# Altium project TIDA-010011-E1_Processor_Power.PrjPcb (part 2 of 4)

## Sheet TIDA-010011-E1_Processor_Power _Pg5.SchDoc: COMPACT POWER MODULE
size 431 x 279 mm; Date: Not shown in title block; ApprovedBy: Not shown in title block; CheckedBy: Not shown in title block; Author: Not shown in title block; CompanyName: Not shown in title block; DrawnBy: Sreenivasa; Engineer: Not shown in title block; Organization: Not shown in title block; Address1: Not shown in title block; Address2: Not shown in title block; Address3: Not shown in title block; Address4: Not shown in title block; DocumentNumber: 1; Revision: Use project parameter SCH_Rev; SheetNumber: 5; SheetTotal: 12; PageSetup: Record=PageOptions¦CenterHorizontal=True¦CenterVertical=True¦PrintScale=0.62¦XCorrection=1.00¦YCorrection=1.00¦PrintKind=0¦BorderSize=5000000¦LeftOffset=0¦BottomOffset=0¦Orientation=2¦PaperLength=1000¦PaperWidth=1000¦Scale=100¦PaperSource=15¦PrintQuality=600¦MediaType=1¦DitherType=10¦PrintScaleMode=1¦PaperKind=Letter
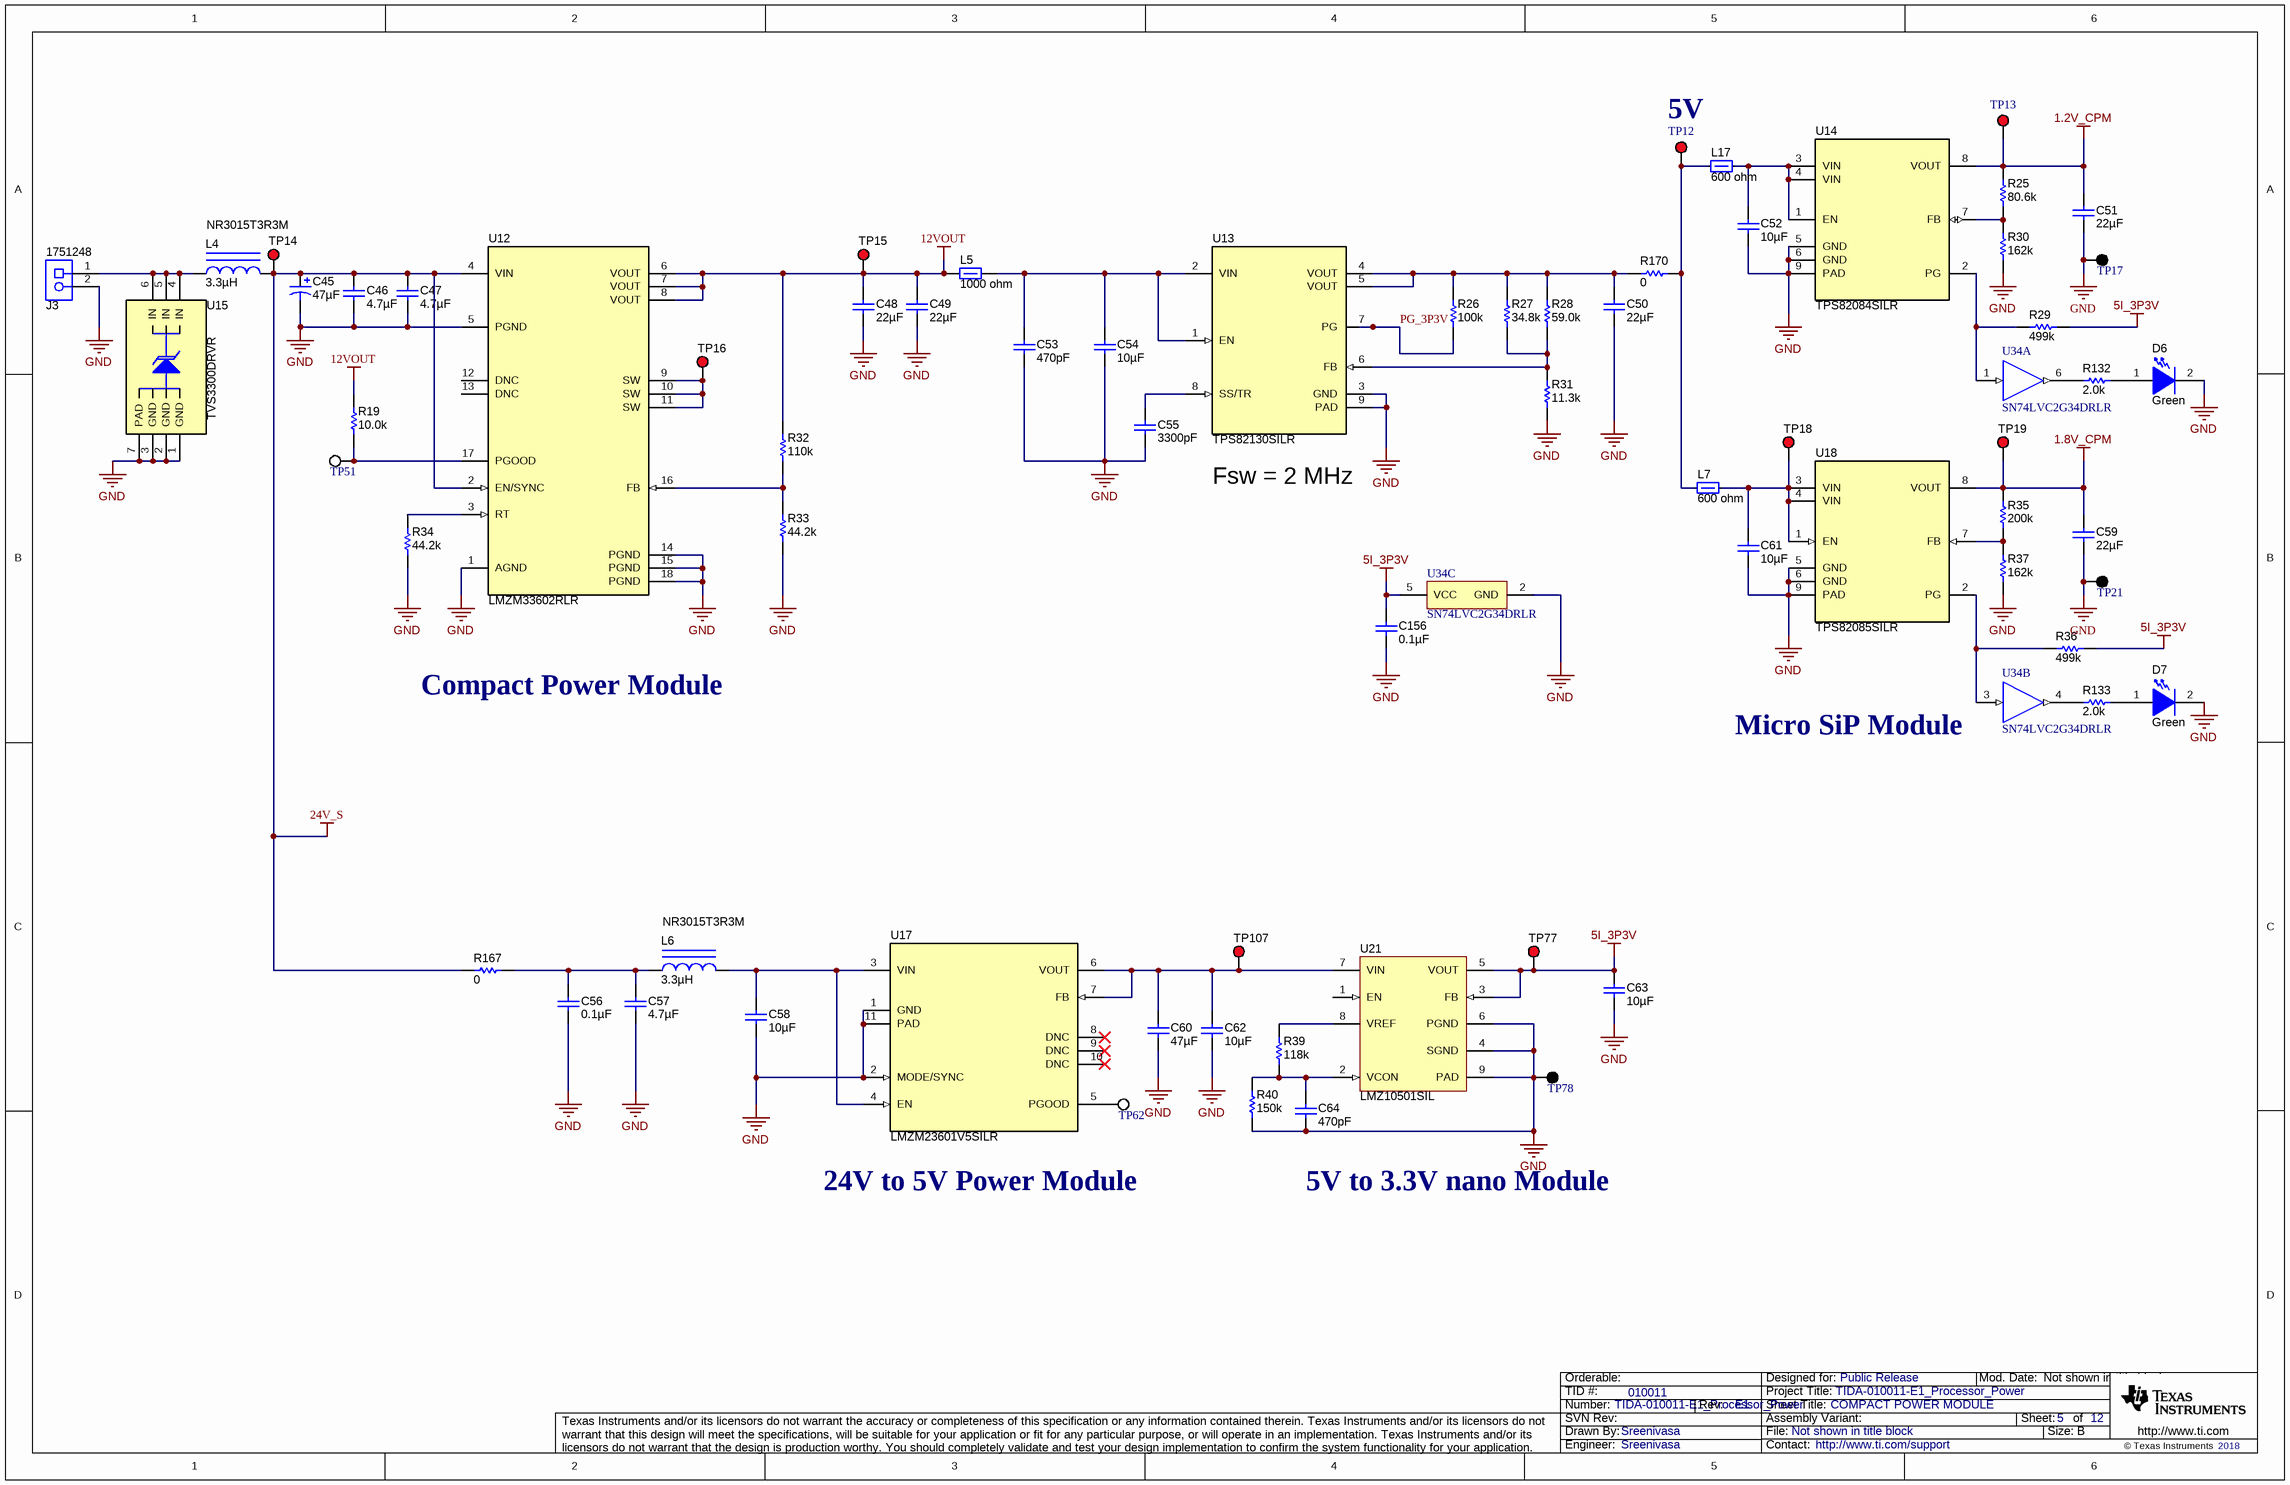
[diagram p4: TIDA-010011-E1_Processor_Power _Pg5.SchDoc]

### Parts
C45  ValueDisplayed: 47µF  [KZN_800x1500]  (hidden comment: EKZN101ELL470MH15D)
C46  ValueDisplayed: 4.7µF  [1210_270]  (hidden comment: GRM32ER71H475KA88L)
C47  ValueDisplayed: 4.7µF  [1210_270]  (hidden comment: GRM32ER71H475KA88L)
C48  ValueDisplayed: 22µF  [1210_270]  (hidden comment: GRM32ER71E226KE15L)
C49  ValueDisplayed: 22µF  [1210_270]  (hidden comment: GRM32ER71E226KE15L)
C50  ValueDisplayed: 22µF  [0805_HV]  (hidden comment: JMK212BJ226MG-T)
C51  ValueDisplayed: 22µF  [0805_HV]  (hidden comment: JMK212BJ226KG-T)
C52  ValueDisplayed: 10µF  [0805_HV]  (hidden comment: GRM21BR71A106KE51L)
C53  ValueDisplayed: 470pF  [0402]  (hidden comment: GRM1555C1H471JA01D)
C54  ValueDisplayed: 10µF  [1206_190]  (hidden comment: C3216X7R1E106M160AE)
C55  ValueDisplayed: 3300pF  [0603]  (hidden comment: GRM1885C1H332JA01D)
C56  ValueDisplayed: 0.1µF  [0805_HV]  (hidden comment: C2012X7R2A104K125AA)
C57  ValueDisplayed: 4.7µF  [1206]  (hidden comment: C3216X7R1V475K085AC)
C58  ValueDisplayed: 10µF  [1206_180]  (hidden comment: CL31B106KBHNNNE)
C59  ValueDisplayed: 22µF  [0805_HV]  (hidden comment: JMK212BJ226KG-T)
C60  ValueDisplayed: 47µF  [1206]  (hidden comment: C3216X5R1C476M160AB)
C61  ValueDisplayed: 10µF  [0805_HV]  (hidden comment: GRM21BR71A106KE51L)
C62  ValueDisplayed: 10µF  [0603]  (hidden comment: C1608X5R1E106M080AC)
C63  ValueDisplayed: 10µF  [0603]  (hidden comment: C1608X5R1E106M080AC)
C64  ValueDisplayed: 470pF  [0603]  (hidden comment: GRM188R71H471KA01D)
C156  ValueDisplayed: 0.1µF  [0603]  (hidden comment: 06033D104KAT2A)
D6  value Green  [LED_LTST-C190_G]  (hidden comment: LTST-C190KGKT)
D7  value Green  [LED_LTST-C190_G]  (hidden comment: LTST-C190KGKT)
J3  1751248  [CONN_1751248]
L4  NR3015T3R3M  ValueDisplayed: 3.3µH  [NR3015]
L5  ValueDisplayed: 1000 ohm  [1806_HighSpeed]  (hidden comment: BLM41PG102SN1L)
L6  NR3015T3R3M  ValueDisplayed: 3.3µH  [NR3015]
L7  value 600 ohm  [0805_HV]  (hidden comment: MPZ2012S601A)
L17  value 600 ohm  [0805_HV]  (hidden comment: MPZ2012S601A)
R19  ValueDisplayed: 10.0k  [0402]  (hidden comment: CRCW040210K0FKED)
R25  ValueDisplayed: 80.6k  [0603]  (hidden comment: RC0603FR-0780K6L)
R26  ValueDisplayed: 100k  [0402]  (hidden comment: CRCW0402100KFKED)
R27  ValueDisplayed: 34.8k  [0603]  (hidden comment: CRCW060334K8FKEA)
R28  ValueDisplayed: 59.0k  [0402]  (hidden comment: CRCW040259K0FKED)
R29  ValueDisplayed: 499k  [0603]  (hidden comment: ERJ-3EKF4993V)
R30  ValueDisplayed: 162k  [0603]  (hidden comment: RC0603FR-07162KL)
R31  ValueDisplayed: 11.3k  [0402]  (hidden comment: CRCW040211K3FKED)
R32  ValueDisplayed: 110k  [0603]  (hidden comment: RC0603FR-07110KL)
R33  ValueDisplayed: 44.2k  [0603]  (hidden comment: CRCW060344K2FKEA)
R34  ValueDisplayed: 44.2k  [0603]  (hidden comment: CRCW060344K2FKEA)
R35  ValueDisplayed: 200k  [0603]  (hidden comment: RC0603FR-07200KL)
R36  ValueDisplayed: 499k  [0603]  (hidden comment: ERJ-3EKF4993V)
R37  ValueDisplayed: 162k  [0603]  (hidden comment: RC0603FR-07162KL)
R39  ValueDisplayed: 118k  [0402]  (hidden comment: CRCW0402118KFKED)
R40  ValueDisplayed: 150k  [0402]  (hidden comment: CRCW0402150KFKED)
R132  ValueDisplayed: 2.0k  [0603]  (hidden comment: CRCW06032K00JNEA)
R133  ValueDisplayed: 2.0k  [0603]  (hidden comment: CRCW06032K00JNEA)
R167  ValueDisplayed: 0  [0805_HV]  (hidden comment: CRCW08050000Z0EA)
R170  ValueDisplayed: 0  [0805_HV]  (hidden comment: CRCW08050000Z0EA)
TP12  5000  [Keystone5000]  (value not drawn)
TP13  5000  [Keystone5000]  (value not drawn)
TP14  (no value)  [Keystone5000]
TP15  (no value)  [Keystone5000]
TP16  (no value)  [Keystone5000]
TP17  5001  [Keystone5001]  (value not drawn)
TP18  (no value)  [Keystone5000]
TP19  (no value)  [Keystone5000]
TP21  5001  [Keystone5001]  (value not drawn)
TP51  5002  [Keystone5002]  (value not drawn)
TP62  5002  [Keystone5002]  (value not drawn)
TP77  (no value)  [Keystone5000]
TP78  5001  [Keystone5001]  (value not drawn)
TP107  (no value)  [Keystone5000]
U12  LMZM33602RLR  [RLR0018A]
U13  TPS82130SILR  [SIL0008D_SMD]
U14  TPS82084SILR  [SIL0008C_SMD]
U15  TVS3300DRVR  [DRV0006A]
U17  LMZM23601V5SILR  [SIL0010A]
U18  TPS82085SILR  [SIL0008C_SMD]
U21  LMZ10501SIL  [SIL0008A]
U34  SN74LVC2G34DRLR  [DRL0006A]  (parts A,B,C of 3)

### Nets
1.2V_CPM: C51.1 R25.2 TP13.1 U14.8(VOUT)
1.8V_CPM: C59.1 R35.2 TP19.1 U18.8(VOUT)
5I_3P3V: C63.1 C156.1 R29.2 R36.1 TP77.1 U21.3(FB) U21.5(VOUT) U34.5(VCC)
12VOUT: C48.1 C49.1 L5.2 R19.2 R32.2 TP15.1 U12.6(VOUT) U12.7(VOUT) U12.8(VOUT)
24V_S: C45.1(+) C46.1 C47.1 L4.2 R167.2 TP14.1 U12.2(EN/SYNC) U12.4(VIN)
GND: C45.2(-) C46.2 C47.2 C48.2 C49.2 C50.2 C51.2 C52.2 C53.2 C54.2 C55.1 C56.2 C57.2 C58.2 C59.2 C60.2 C61.2 C62.2 C63.2 C64.2 C156.2 D6.2(K) D7.2(K) J3.2 R30.1 R31.1 R33.1 R34.1 R37.1 R40.1 TP17.1 TP21.1 TP78.1 U12.1(AGND) U12.5(PGND) U12.14(PGND) U12.15(PGND) U12.18(PGND) U13.3(GND) U13.9(PAD) U14.5(GND) U14.6(GND) U14.9(PAD) U15.1(GND) U15.2(GND) U15.3(GND) U15.7(PAD) U17.1(GND) U17.2(MODE/SYNC) U17.11(PAD) U18.5(GND) U18.6(GND) U18.9(PAD) U21.4(SGND) U21.6(PGND) U21.9(PAD) U34.2(GND)
PG_3P3V: R26.1 U13.7(PG)
NetC50_1: C50.1 R26.2 R27.2 R28.2 R170.2 U13.4(VOUT) U13.5(VOUT)
NetC52_1: C52.1 L17.1 U14.1(EN) U14.3(VIN) U14.4(VIN)
NetC53_1: C53.1 C54.1 L5.1 U13.1(EN) U13.2(VIN)
NetC55_2: C55.2 U13.8(SS/TR)
NetC56_1: C56.1 C57.1 L6.1 R167.1
NetC58_1: C58.1 L6.2 U17.3(VIN) U17.4(EN)
NetC60_1: C60.1 C62.1 TP107.1 U17.6(VOUT) U17.7(FB) U21.7(VIN)
NetC61_1: C61.1 L7.1 TP18.1 U18.1(EN) U18.3(VIN) U18.4(VIN)
NetC64_1: C64.1 R39.1 R40.2 U21.2(VCON)
NetD6_1: D6.1(A) R132.2
NetD7_1: D7.1(A) R133.2
NetJ3_1: J3.1 L4.1 U15.4(IN) U15.5(IN) U15.6(IN)
NetL7_2: L7.2 L17.2 R170.1 TP12.1
NetR19_1: R19.1 TP51.1 U12.17(PGOOD)
NetR25_1: R25.1 R30.2 U14.7(FB)
NetR27_1: R27.1 R28.1 R31.2 U13.6(FB)
NetR29_1: R29.1 U14.2(PG) U34.1(1A)
NetR32_1: R32.1 R33.2 U12.16(FB)
NetR34_2: R34.2 U12.3(RT)
NetR35_1: R35.1 R37.2 U18.7(FB)
NetR36_2: R36.2 U18.2(PG) U34.3(2A)
NetR39_2: R39.2 U21.8(VREF)
NetR132_1: R132.1 U34.6(1Y)
NetR133_1: R133.1 U34.4(2Y)
NetTP16_1: TP16.1 U12.9(SW) U12.10(SW) U12.11(SW)
NetTP62_1: TP62.1 U17.5(PGOOD)

Not connected (* = marked no-connect by the designer): U12 12(DNC) 13(DNC); U17 8(DNC)* 9(DNC)* 10(DNC)*; U21 1(EN)

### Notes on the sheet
- 5V
- Fsw = 2 MHz
- Compact Power Module
- (near U34) Micro SiP Module
- 24V to 5V Power Module
- 5V to 3.3V nano Module

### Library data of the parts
C45 = EKZN101ELL470MH15D: CAP, AL, 47 µF, 100 V, +/- 20%, 0.14 ohm, TH; Manufacturer: Chemi-Con; Polarized: Y; CompType: Capacitor; Value: 47uF; U/M: EA; Cap_F: 0.000047; Tolerance_%: 20; VDC_V: 100; Value2: 100V; ESR_ohm: 0.14; IRMS_A: 0.78; TaMin_C: -40; TaMax_C: 105; Cap_Case: 8x15mm; SizeArea_mm2: 64; SizeX_mm: 8; SizeZ_mm: 16.5; AEC Category: Q200; AEC Qualified: N
C46 C47 = GRM32ER71H475KA88L: CAP, CERM, 4.7 µF, 50 V,+/- 10%, X7R, 1210; Manufacturer: MuRata; Polarized: N; CompType: Capacitor; Value: 4.7uF; U/M: EA; Cap_F: 0.0000047; Tolerance_%: 10; ESR_ohm: 0.002; Value1: 0.002 ohm; VDC_V: 50; Value2: 50V; TaMin_C: -55; TaMax_C: 125; Cap_Case: 1210; SizeArea_mm2: 8; SizeAreaWB_mm2: 14.7; SizeX_mm: 3.2; SizeY_mm: 2.5; SizeZ_mm: 2.7; AEC Category: Q200; Green_Lifecycle: Active; Green_REACh: Passed
C48 C49 = GRM32ER71E226KE15L: CAP, CERM, 22 µF, 25 V,+/- 10%, X7R, 1210; Manufacturer: MuRata; Polarized: N; CompType: Capacitor; Value: 22uF; U/M: EA; Cap_F: 0.000022; Tolerance_%: 10; ESR_ohm: 0.002334; Value1: 0.002334 ohm; VDC_V: 25; Value2: 25V; IRMS_A: 3.832999; TaMin_C: -55; TaMax_C: 125; Cap_Case: 1210; SizeArea_mm2: 8; SizeAreaWB_mm2: 14.7; SizeX_mm: 3.2; SizeY_mm: 2.5; SizeZ_mm: 2.7; AEC Category: Q200; Green_Lifecycle: Active; Green_REACh: Passed
C50 = JMK212BJ226MG-T: CAP, CERM, 22 µF, 6.3 V, +/- 20%, X5R, 0805; Manufacturer: Taiyo Yuden; Polarized: N; CompType: Capacitor; Value: 22uF; U/M: EA; Cap_F: 0.000022; Tolerance_%: 20; Value1: Unknown; VDC_V: 6.3; Value2: 6.3V; TaMin_C: -55; TaMax_C: 85; Cap_Case: 0805; SizeArea_mm2: 2.5; SizeAreaWB_mm2: 6.75; SizeX_mm: 2; SizeY_mm: 1.25; SizeZ_mm: 1.45; AEC Category: Q200
C51 C59 = JMK212BJ226KG-T: CAP, CERM, 22 µF, 6.3 V, +/- 10%, X5R, 0805; Manufacturer: Taiyo Yuden; Polarized: N; CompType: Capacitor; Value: 22uF; U/M: EA; Cap_F: 0.000022; Tolerance_%: 10; ESR_ohm: 0.002; Value1: 0.002 ohm; VDC_V: 6.3; Value2: 6.3V; TaMin_C: -55; TaMax_C: 85; Cap_Case: 0805; SizeArea_mm2: 2.5; SizeAreaWB_mm2: 6.75; SizeX_mm: 2; SizeY_mm: 1.25; SizeZ_mm: 1.45; AEC Category: Q200
C52 C61 = GRM21BR71A106KE51L: CAP, CERM, 10 µF, 10 V, +/- 10%, X7R, 0805; Manufacturer: MuRata; Polarized: N; CompType: Capacitor; Value: 10uF; U/M: EA; Cap_F: 0.00001; Tolerance_%: 10; ESR_ohm: 0.003; Value1: 0.003 ohm; Value2: 10V; TaMin_C: -55; TaMax_C: 125; Cap_Case: 0805; SizeArea_mm2: 2.5; SizeAreaWB_mm2: 6.75; SizeX_mm: 2; SizeY_mm: 1.25; SizeZ_mm: 1.45; AEC Category: Q200
C53 = GRM1555C1H471JA01D: CAP, CERM, 470 pF, 50 V, +/- 5%, C0G/NP0, 0402; Manufacturer: MuRata; Polarized: N; CompType: Capacitor; Value: 470pF; U/M: EA; Cap_F: 0.00000000047; Tolerance_%: 5; Value1: Unknown; VDC_V: 50; Value2: 50V; TaMin_C: -55; TaMax_C: 125; SizeArea_mm2: 0.5; SizeAreaWB_mm2: 3; SizeX_mm: 1; SizeZ_mm: 0.6; AEC Category: Q200
C54 = C3216X7R1E106M160AE: CAP, CERM, 10 µF, 25 V, +/- 20%, X7R, 1206_190; Manufacturer: TDK; Polarized: N; CompType: Capacitor; Value: 10uF; U/M: EA; Cap_F: 0.00001; Tolerance_%: 20; Value1: Unknown; VDC_V: 25; Value2: 25V; TaMin_C: -55; TaMax_C: 125; Cap_Case: 1206; SizeArea_mm2: 5.12; SizeAreaWB_mm2: 10.92; SizeX_mm: 3.2; SizeY_mm: 1.6; SizeZ_mm: 1.9; AEC Category: Q200
C55 = GRM1885C1H332JA01D: CAP, CERM, 3300 pF, 50 V, +/- 5%, C0G/NP0, 0603; Manufacturer: MuRata; Polarized: N; CompType: Capacitor; Value: 3300pF; U/M: EA; Cap_F: 0.0000000033; Tolerance_%: 5; Value1: Unknown; VDC_V: 50; Value2: 50V; TaMin_C: -55; TaMax_C: 125; SizeArea_mm2: 1.28; SizeAreaWB_mm2: 4.68; SizeX_mm: 1.6; SizeY_mm: 0.8; SizeZ_mm: 1; AEC Category: Q200
C56 = C2012X7R2A104K125AA: CAP, CERM, 0.1 µF, 100 V, +/- 10%, X7R, 0805; Manufacturer: TDK; Polarized: N; CompType: Capacitor; Value: 0.1uF; U/M: EA; Cap_F: 0.0000001; Tolerance_%: 10; ESR_ohm: 0.020726; Value1: 0.020726 ohm; VDC_V: 100; Value2: 100V; IRMS_A: 1.456; TaMin_C: -55; TaMax_C: 125; Cap_Case: 0805; SizeArea_mm2: 2.5; SizeAreaWB_mm2: 6.75; SizeX_mm: 2; SizeY_mm: 1.25; SizeZ_mm: 1.45; AEC Category: Q200
C57 = C3216X7R1V475K085AC: CAP, CERM, 4.7 µF, 35 V, +/- 10%, X7R, 1206; Manufacturer: TDK; Polarized: N; CompType: Capacitor; Value: 4.7uF; U/M: EA; Cap_F: 0.0000047; Tolerance_%: 10; ESR_ohm: 0.003785; Value1: 0.003785 ohm; VDC_V: 35; Value2: 35V; IRMS_A: 3.73011; TaMin_C: -55; TaMax_C: 125; SizeArea_mm2: 5.12; SizeAreaWB_mm2: 10.92; SizeX_mm: 3.2; SizeY_mm: 1.6; SizeZ_mm: 1.35; AEC Category: Q200
C58 = CL31B106KBHNNNE: CAP, CERM, 10 µF, 50 V,+/- 10%, X7R, 1206; Manufacturer: Samsung Electro-Mechanics; Polarized: N; CompType: Capacitor; Value: 10uF; U/M: EA; Cap_F: 0.00001; Tolerance_%: 10; VDC_V: 50; Value2: 50V; TaMin_C: -55; TaMax_C: 125; Cap_Case: 1206; SizeArea_mm2: 5.12; SizeAreaWB_mm2: 10.92; SizeX_mm: 3.2; SizeY_mm: 1.6; SizeZ_mm: 1.8; AEC Category: Q200
C60 = C3216X5R1C476M160AB: CAP, CERM, 47 µF, 16 V,+/- 15%, X5R, 1206; Manufacturer: TDK; Polarized: N; CompType: Capacitor; Value: 47uF; U/M: EA; Cap_F: 0.000047; Tolerance_%: 15; VDC_V: 16; Value2: 16V; TaMin_C: -55; TaMax_C: 85; SizeArea_mm2: 5.12; SizeAreaWB_mm2: 10.92; SizeX_mm: 3.2; SizeY_mm: 1.6; SizeZ_mm: 1.35; AEC Category: Q200; Green_Lifecycle: Active; Green_REACh: Passed
C62 C63 = C1608X5R1E106M080AC: CAP, CERM, 10 µF, 25 V, +/- 20%, X5R, 0603; Manufacturer: TDK; Polarized: N; CompType: Capacitor; Value: 10uF; U/M: EA; Cap_F: 0.00001; Tolerance_%: 20; Value1: Unknown; VDC_V: 25; Value2: 25V; TaMin_C: -55; TaMax_C: 85
C64 = GRM188R71H471KA01D: CAP, CERM, 470 pF, 50 V,+/- 10%, X7R, 0603; Manufacturer: MuRata; Polarized: N; CompType: Capacitor; Value: 470pF; U/M: EA; Cap_F: 0.00000000047; Tolerance_%: 10; VDC_V: 50; Value2: 50V; TaMin_C: -55; TaMax_C: 125; SizeArea_mm2: 1.28; SizeAreaWB_mm2: 4.68; SizeX_mm: 1.6; SizeY_mm: 0.8; SizeZ_mm: 1; AEC Category: Q200; Green_Lifecycle: Active; Green_REACh: Passed
C156 = 06033D104KAT2A: CAP, CERM, 0.1 µF, 25 V,+/- 10%, X5R, 0603; Manufacturer: AVX; Polarized: N; CompType: Capacitor; Value: 0.1uF; U/M: EA; Cap_F: 0.0000001; Tolerance_%: 10; ESR_ohm: 0.048; Value1: 0.048 ohm; VDC_V: 25; Value2: 25V; IRMS_A: 0.53; TaMin_C: -55; TaMax_C: 85; SizeArea_mm2: 1.28; SizeAreaWB_mm2: 4.68; SizeX_mm: 1.6; SizeY_mm: 0.8; SizeZ_mm: 1; AEC Category: Q200; Green_Lifecycle: Active; Green_REACh: Passed
D6 D7 = LTST-C190KGKT: LED, Green, SMD; Manufacturer: Lite-On; Type: AlInGaP; Vf_V: 2; Value2: 2V; Io_A: 0.03; Tjmax_C: 85; Value1: W; U/M: EA
J3 = 1751248: Conn Term Block, 2POS, 3.5mm, TH; Manufacturer: Phoenix Contact; CompType: Terminal Block; SymbolCreator: a0412235
L4 L6 = NR3015T3R3M: Inductor, Wirewound, Ferrite, 3.3 µH, 1.21 A, 0.096 ohm, AEC-Q200 Grade 2, SMD; Manufacturer: Taiyo Yuden; Value: 3.3uH; Imax_A: 1.21; DCR_ohm: 0.096; Value2: 1.21A; Ind_H: 3.3E-6; Irms: 1.23A @ 40C rise; Isat: 1.21A @ 30% inductance drop; SizeAreaWB_mm2: 16; SizeArea_mm2: 9; SizeX_mm: 3; SizeZ_mm: 1.5; AEC Category: Q200; AEC Qualified: Y; AEC Grade: 2
L5 = BLM41PG102SN1L: Ferrite Bead, 1000 ohm @ 100 MHz, 1.5 A, 1806; Manufacturer: MuRata; Imax_A: 1.5; DCR_ohm: 0.09; Value1: 0.09 ohm; Value2: 1.5A; SizeAreaWB_mm2: 14.3; SizeArea_mm2: 7.2; SizeX_mm: 4.5; SizeY_mm: 1.6; SizeZ_mm: 1.85; ZTyp@100MHz_Ohm: 1000
L7 L17 = MPZ2012S601A: Ferrite Bead, 600 ohm @ 100MHz, 2A, 0805; Manufacturer: TDK; Imax_A: 2; DCR_ohm: 0.1; Value1: 0.1 ohm; ZTyp@100MHz_Ohm: 600
R19 = CRCW040210K0FKED: RES, 10.0 k, 1%, 0.063 W, 0402; Manufacturer: Vishay-Dale; CompType: Resistor; Value: 10.0k; Res_ohm: 10000; Value_Code: 10k0; Tolerance_%: 1; Power_W: 0.063; Value2: 0.063W; VDC_V: 50; TempCo: 100 ppm/C; EIA_Code: E96; U/M: EA
R25 = RC0603FR-0780K6L: RES, 80.6 k, 1%, 0.1 W, 0603; Manufacturer: Yageo America; CompType: Resistor; Value: 80.6k; Res_ohm: 80600; Value_Code: 80k6; Tolerance_%: 1; Power_W: 0.1; Value2: 0.1W; VDC_V: 150; TempCo: 200 ppm/C; SizeArea_mm2: 1.28; SizeX_mm: 1.6; SizeY_mm: 0.8; EIA_Code: E96; U/M: EA; AEC Category: Q200; Green_Lifecycle: Active; Green_REACh: Passed
R26 = CRCW0402100KFKED: RES, 100 k, 1%, 0.063 W, 0402; Manufacturer: Vishay-Dale; CompType: Resistor; Value: 100k; Res_ohm: 100000; Tolerance_%: 1; Power_W: 0.063; Value2: 0.063W; VDC_V: 50; TempCo: 100 ppm/C; SizeArea_mm2: 0.5; SizeZ_mm: 0.6; EIA_Code: E96; U/M: EA; AEC Category: Q200
R27 = CRCW060334K8FKEA: RES, 34.8 k, 1%, 0.1 W, 0603; Manufacturer: Vishay-Dale; CompType: Resistor; Value: 34.8k; Res_ohm: 34800; Value_Code: 34k8; Tolerance_%: 1; Power_W: 0.1; Value2: 0.1W; VDC_V: 75; TempCo: 100 ppm/C; SizeArea_mm2: 1.28; SizeX_mm: 1.6; SizeY_mm: 0.8; EIA_Code: E96; U/M: EA; AEC Category: Q200
R28 = CRCW040259K0FKED: RES, 59.0 k, 1%, 0.063 W, 0402; Manufacturer: Vishay-Dale; CompType: Resistor; Value: 59.0k; Res_ohm: 59000; Value_Code: 59k0; Tolerance_%: 1; Power_W: 0.063; Value2: 0.063W; VDC_V: 50; TempCo: 100 ppm/C; SizeArea_mm2: 0.5; SizeZ_mm: 0.6; EIA_Code: E96; U/M: EA; AEC Category: Q200
R29 R36 = ERJ-3EKF4993V: RES, 499 k, 1%, 0.1 W, AEC-Q200 Grade 0, 0603; Manufacturer: Panasonic; CompType: Resistor; Value: 499k; Res_ohm: 499000; Tolerance_%: 1; Power_W: 0.1; Value2: 0.1W; VDC_V: 75; TempCo: 100 ppm/C; SizeArea_mm2: 1.28; SizeX_mm: 1.6; SizeY_mm: 0.8; EIA_Code: E96; U/M: EA; AEC Category: Q200; AEC Qualified: Y; AEC Grade: 0; Green_Lifecycle: Active; Green_REACh: Passed
R30 R37 = RC0603FR-07162KL: RES, 162 k, 1%, 0.1 W, 0603; Manufacturer: Yageo America; CompType: Resistor; Value: 162k; Res_ohm: 162000; Tolerance_%: 1; Power_W: 0.1; Value2: 0.1W; VDC_V: 150; TempCo: 200 ppm/C; SizeArea_mm2: 1.28; SizeX_mm: 1.6; SizeY_mm: 0.8; EIA_Code: E96; U/M: EA; AEC Category: Q200; Green_Lifecycle: Active; Green_REACh: Passed
R31 = CRCW040211K3FKED: RES, 11.3 k, 1%, 0.063 W, 0402; Manufacturer: Vishay-Dale; CompType: Resistor; Value: 11.3k; Res_ohm: 11300; Value_Code: 11k3; Tolerance_%: 1; Power_W: 0.063; Value2: 0.063W; VDC_V: 50; TempCo: 100 ppm/C; SizeArea_mm2: 0.5; SizeZ_mm: 0.6; EIA_Code: E96; U/M: EA; AEC Category: Q200
R32 = RC0603FR-07110KL: RES, 110 k, 1%, 0.1 W, 0603; Manufacturer: Yageo America; CompType: Resistor; Value: 110k; Res_ohm: 110000; Tolerance_%: 1; Power_W: 0.1; Value2: 0.1W; VDC_V: 150; TempCo: 200 ppm/C; SizeArea_mm2: 1.28; SizeX_mm: 1.6; SizeY_mm: 0.8; EIA_Code: E96; U/M: EA; AEC Category: Q200
R33 R34 = CRCW060344K2FKEA: RES, 44.2 k, 1%, 0.1 W, 0603; Manufacturer: Vishay-Dale; CompType: Resistor; Value: 44.2k; Res_ohm: 44200; Value_Code: 44k2; Tolerance_%: 1; Power_W: 0.1; Value2: 0.1W; VDC_V: 75; TempCo: 100 ppm/C; SizeArea_mm2: 1.28; SizeX_mm: 1.6; SizeY_mm: 0.8; EIA_Code: E96; U/M: EA; AEC Category: Q200; Green_Lifecycle: Active; Green_REACh: Passed
R35 = RC0603FR-07200KL: RES, 200 k, 1%, 0.1 W, 0603; Manufacturer: Yageo America; CompType: Resistor; Value: 200k; Res_ohm: 200000; Tolerance_%: 1; Power_W: 0.1; Value2: 0.1W; VDC_V: 150; TempCo: 200 ppm/C; SizeArea_mm2: 1.28; SizeX_mm: 1.6; SizeY_mm: 0.8; EIA_Code: E96; U/M: EA; AEC Category: Q200; Green_Lifecycle: Active; Green_REACh: Passed
R39 = CRCW0402118KFKED: RES, 118 k, 1%, 0.063 W, 0402; Manufacturer: Vishay-Dale; CompType: Resistor; Value: 118k; Res_ohm: 118000; Tolerance_%: 1; Power_W: 0.063; Value2: 0.063W; VDC_V: 50; TempCo: 100 ppm/C; SizeArea_mm2: 0.5; SizeZ_mm: 0.6; EIA_Code: E96; U/M: EA; AEC Category: Q200; Green_Lifecycle: Active; Green_REACh: Passed
R40 = CRCW0402150KFKED: RES, 150 k, 1%, 0.063 W, 0402; Manufacturer: Vishay-Dale; CompType: Resistor; Value: 150k; Res_ohm: 150000; Tolerance_%: 1; Power_W: 0.063; Value2: 0.063W; VDC_V: 50; TempCo: 100 ppm/C; EIA_Code: E96; U/M: EA
R132 R133 = CRCW06032K00JNEA: RES, 2.0 k, 5%, 0.1 W, 0603; Manufacturer: Vishay-Dale; CompType: Resistor; Value: 2.0k; Res_ohm: 2000; Value_Code: 2k00; Tolerance_%: 5; Power_W: 0.1; Value2: 0.1W; VDC_V: 75; TempCo: 200 ppm/C; SizeArea_mm2: 1.28; SizeX_mm: 1.6; SizeY_mm: 0.8; SizeZ_mm: 1; EIA_Code: E24; U/M: EA; AEC Category: Q200; Green_Lifecycle: Active; Green_REACh: Passed
R167 R170 = CRCW08050000Z0EA: RES, 0, 5%, 0.125 W, 0805; Manufacturer: Vishay-Dale; CompType: Resistor; Value: 0; Value_Code: 0000; Tolerance_%: 5; Power_W: 0.125; Value2: 0.125W; VDC_V: 150; TempCo: 200 ppm/C; SizeArea_mm2: 2.5; SizeX_mm: 2; SizeY_mm: 1.25; SizeZ_mm: 1.45; EIA_Code: E24; U/M: EA; AEC Category: Q200; Green_Lifecycle: Active; Green_REACh: Passed
TP12 TP13 = 5000: Test Point, Miniature, Red, TH; Manufacturer: Keystone; CompType: Test Point Loop; ContactFinish: Silver; Green_Lifecycle: Active; Green_REACh: Passed
TP14-TP16 TP18 TP19 TP77 TP107 = 5000: Test Point, Miniature, Red, TH; Manufacturer: Keystone; CompType: Test Point Loop; ContactFinish: Silver
TP17 TP21 TP78 = 5001: Test Point, Miniature, Black, TH; Manufacturer: Keystone; CompType: Test Point Loop; ContactFinish: Silver; Green_Lifecycle: Active; Green_REACh: Passed
TP51 TP62 = 5002: Test Point, Miniature, White, TH; Manufacturer: Keystone; CompType: Test Point Loop; ContactFinish: Silver; Green_Lifecycle: Active; Green_REACh: Passed
U12 = CMP-0013868-2: LMZM33602, RLR0018A (B2QFN-18); Manufacturer: Texas Instruments; SizeX_mm: 7; SizeY_mm: 9; CompType: IC; SizeZ_mm: 4.1; SizeArea_mm2: 63; SizeAreaWB_mm2: 99; U/M: EA
U13 = TPS82130SILR: 3-A 17V Step-down Converter Module with Integrated Inductor, SIL0008D (uSIP-8); Alternate PartNumber: TPS82130SILT; Manufacturer: Texas Instruments; SymbolCreator: Altium; SizeArea_mm2: 12.25; SizeAreaWB_mm2: 20.25; SizeX_mm: 3.5; SizeZ_mm: 1.53; CompType: IC; U/M: EA
U14 = TPS82084SILR: 2A, High Efficiency Step Down Converter Module with Integrated Inductor, SIL0008C; Alternate PartNumber: TPS82084SILT; Manufacturer: Texas Instruments; SymbolCreator: a0411947; SizeArea_mm2: 12.25; SizeAreaWB_mm2: 20.25; SizeX_mm: 3.5; SizeZ_mm: 1.33; CompType: IC; U/M: EA
U15 = CMP-0013424-7: 33-V Precision Surge Protection Clamp, DRV0006A (WSON-6); Manufacturer: Texas Instruments; Alternate PartNumber: TVS3300DRVT; SizeX_mm: 2; CompType: IC; SizeZ_mm: 0.8; SizeArea_mm2: 4; SizeAreaWB_mm2: 9; U/M: EA
U17 = CMP-0075377-4: 36-V 1-A Step-Down DC-DC Nano Module, SIL0010A (uSIP-10); Manufacturer: Texas Instruments; Alternate PartNumber: LMZM23601V5SILT; SizeAreaWB_mm2: 19.2; SizeArea_mm2: 11.4; AEC Qualified: N; AEC Category: Q200; SizeZ_mm: 1.578; SizeY_mm: 3.0; CompType: IC; SizeX_mm: 3.8
U18 = CMP-0067287-1: 3A, High-Efficiency Step-Down Converter Module with Integrated Inductor, SIL0008C (uSIP-8); Alternate PartNumber: TPS82085SILT; Alternate Manufacturer: Texas Instruments; SizeAreaWB_mm2: 20.25; U/M: EA; SizeZ_mm: 1.33; SizeX_mm: 3.5; SizeArea_mm2: 12.25; CompType: IC
U21 = LMZ10501SIL: 1A SIMPLE SWITCHER® Nano Module with 5.5V Maximum Input Voltage, SIL0008A; Alternate Manufacturer: None; Manufacturer: Texas Instruments; SymbolCreator: a0799628; CompType: IC; U/M: EA
U34 = CMP-0051912-2: Dual Buffer Gate, DRL0006A, LARGE T&R; Manufacturer: Texas Instruments; F @ Nom Voltage(Max)(Mhz): 150; Rating: Catalog; Sub-Family: Non-Inverting Buffer/Driver; VCC(Min)(V): 1.65; Bits(#): 2; Logic: True; 3-State Output: No; Input Type: CMOS/TTL; Output Type: CMOS; Voltage(Nom)(V): 1.8,2.5,3.3,5; VCC(Max)(V): 5.5; Output Drive (IOL/IOH)(Max)(mA): 32/-32; tpd @ Nom Voltage(Max)(ns): 8.6,4.4,4.1,3.2; ICC @ Nom Voltage(Max)(mA): 0.01; Technology Family: LVC; AEC Category: Q200; AEC Qualified: N; CompType: IC; SizeArea_mm2: 2.56; SizeX_mm: 1.6; SizeZ_mm: 0.6

## Sheet TIDA-010011-E1_Processor_Power _Pg6.SchDoc: SUPPLY ORING
size 431 x 279 mm; Date: Not shown in title block; ApprovedBy: Not shown in title block; CheckedBy: Not shown in title block; Author: Not shown in title block; CompanyName: Not shown in title block; DrawnBy: Sreenivasa; Engineer: Not shown in title block; Organization: Not shown in title block; Address1: Not shown in title block; Address2: Not shown in title block; Address3: Not shown in title block; Address4: Not shown in title block; DocumentNumber: 1; Revision: Use project parameter SCH_Rev; SheetNumber: 6; SheetTotal: 12; PageSetup: Record=PageOptions¦CenterHorizontal=True¦CenterVertical=True¦PrintScale=0.62¦XCorrection=1.00¦YCorrection=1.00¦PrintKind=0¦BorderSize=5000000¦LeftOffset=0¦BottomOffset=0¦Orientation=2¦PaperLength=1000¦PaperWidth=1000¦Scale=100¦PaperSource=15¦PrintQuality=600¦MediaType=1¦DitherType=10¦PrintScaleMode=1¦PaperKind=Letter
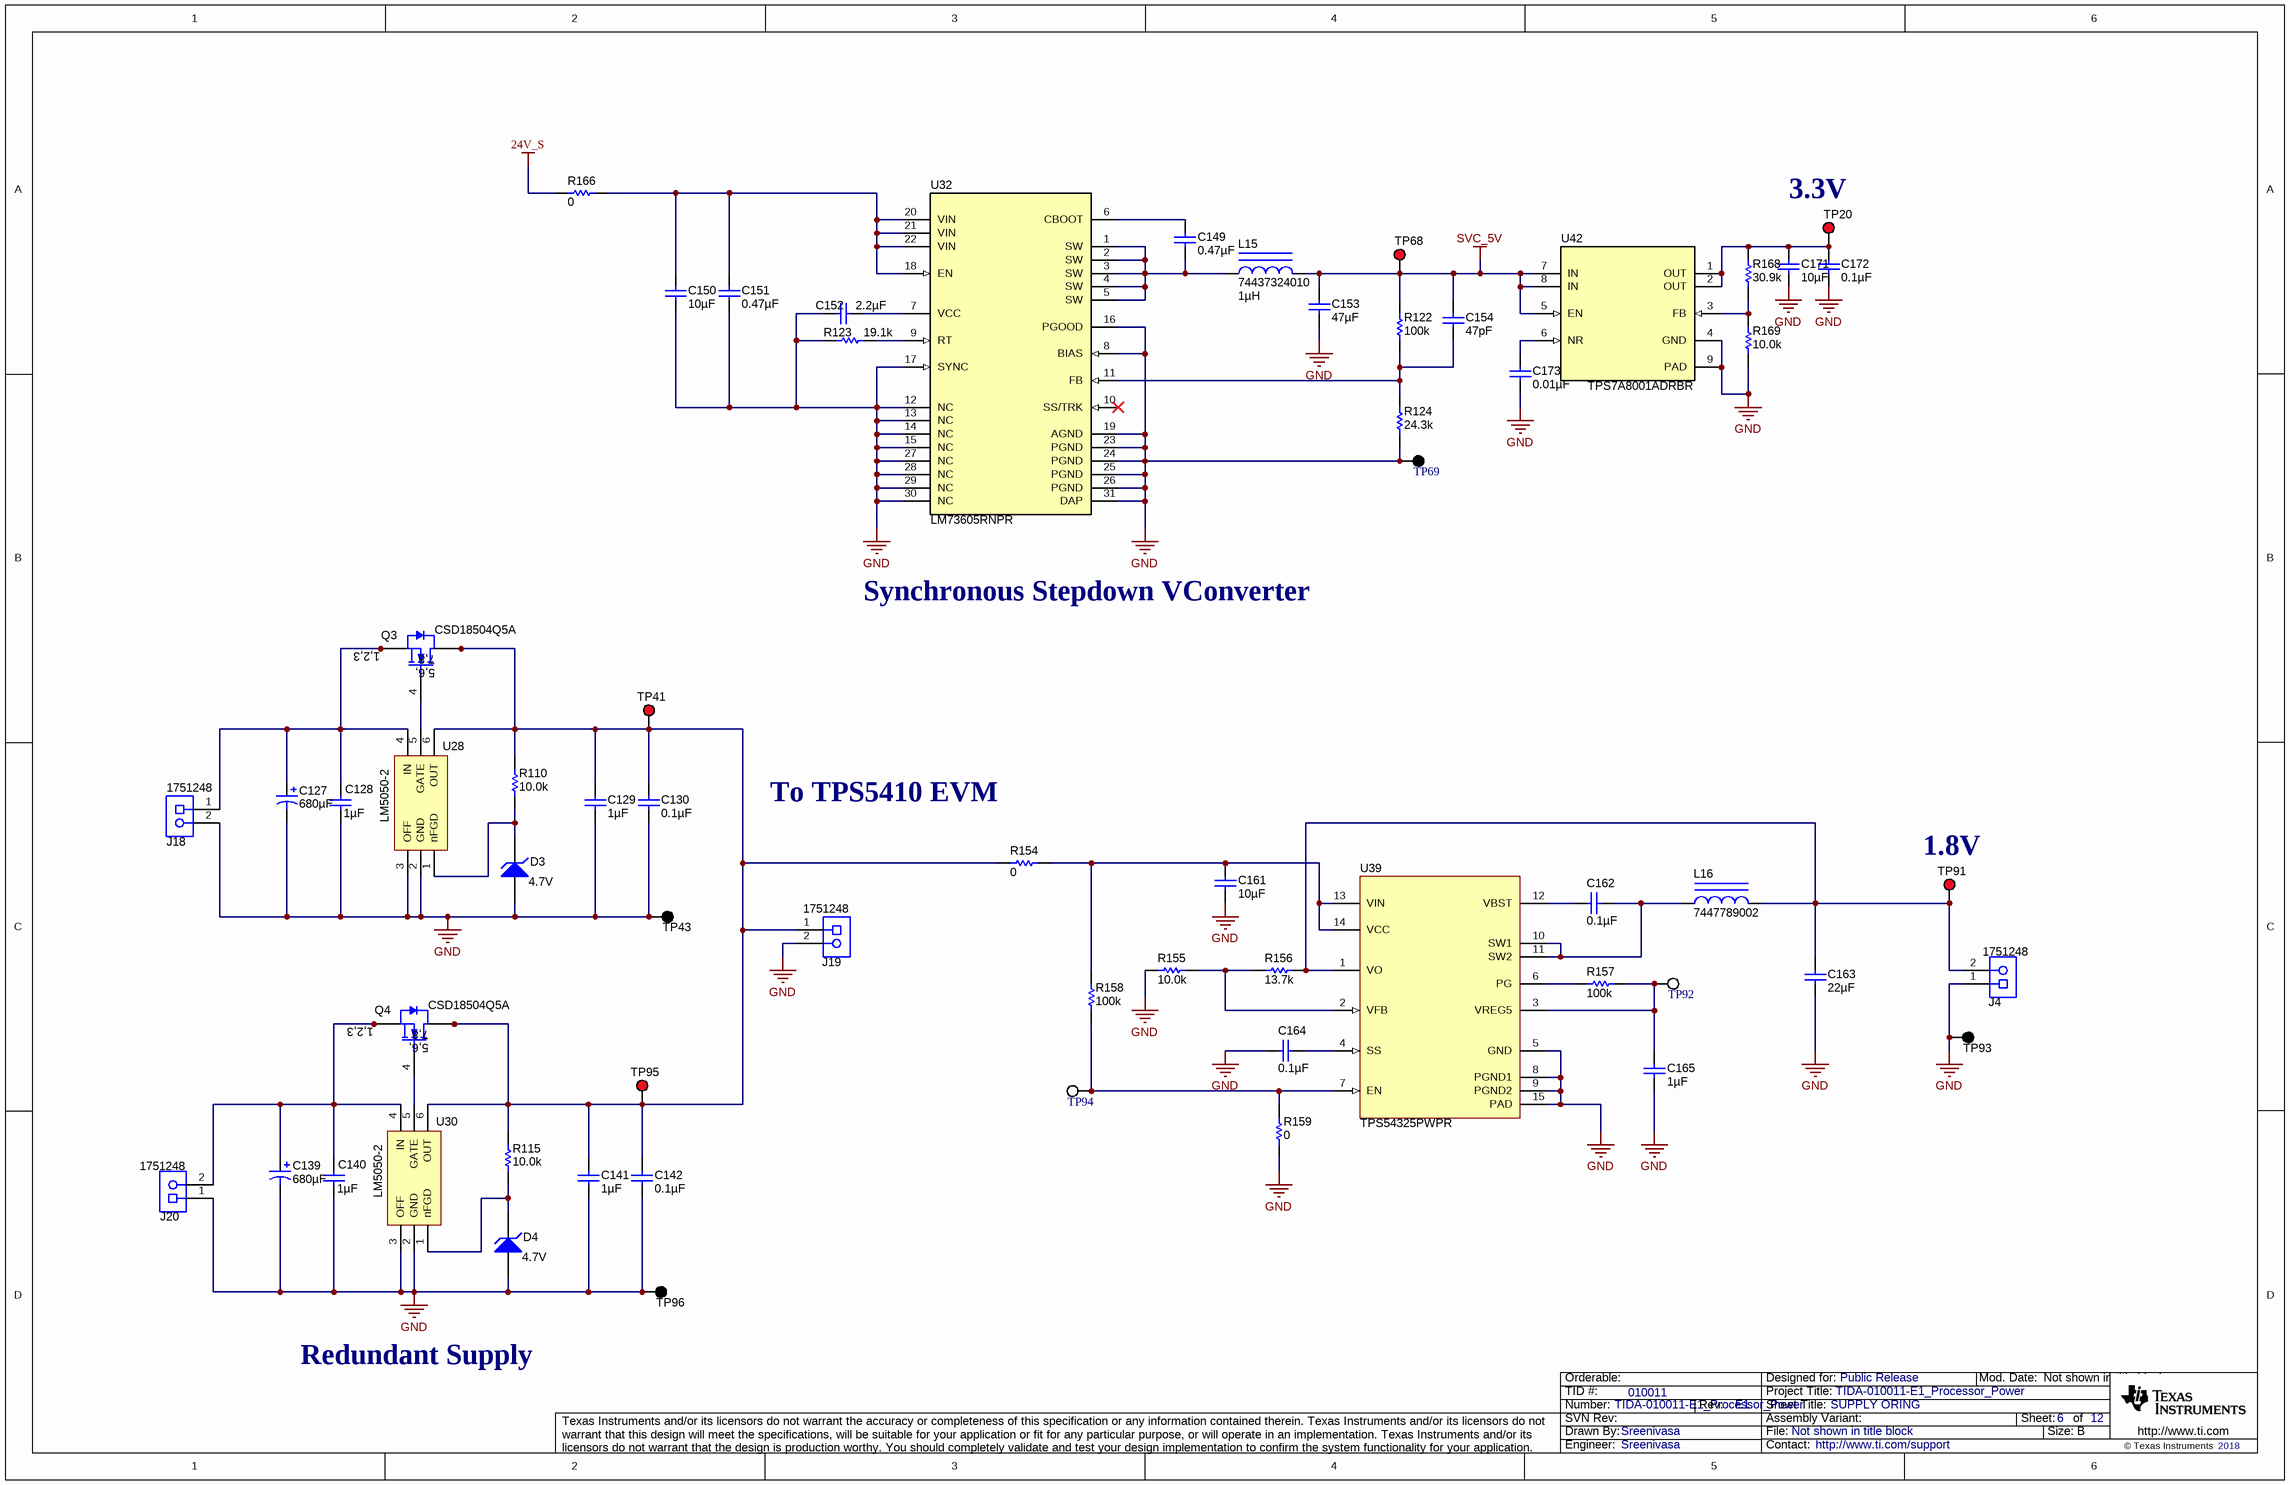
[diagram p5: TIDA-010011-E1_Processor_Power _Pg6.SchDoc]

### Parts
C127  ValueDisplayed: 680µF  [Chemi-Con_1000x2000]  (hidden comment: EKZE250ELL681MJ20S)
C128  ValueDisplayed: 1µF  [0603]  (hidden comment: GRM188R61H105KAALD)
C129  ValueDisplayed: 1µF  [1206]  (hidden comment: C3216X7R1H105K)
C130  ValueDisplayed: 0.1µF  [1206]  (hidden comment: C1206C104J5RACTU)
C139  ValueDisplayed: 680µF  [Chemi-Con_1000x2000]  (hidden comment: EKZE250ELL681MJ20S)
C140  ValueDisplayed: 1µF  [0603]  (hidden comment: GRM188R61H105KAALD)
C141  ValueDisplayed: 1µF  [1206]  (hidden comment: C3216X7R1H105K)
C142  ValueDisplayed: 0.1µF  [1206]  (hidden comment: C1206C104J5RACTU)
C149  ValueDisplayed: 0.47µF  [0603]  (hidden comment: C1608X7R1H474K080AC)
C150  ValueDisplayed: 10µF  [1210_270]  (hidden comment: GRM32ER71H106KA12L)
C151  ValueDisplayed: 0.47µF  [0603]  (hidden comment: C1608X7R1H474K080AC)
C152  ValueDisplayed: 2.2µF  [0603]  (hidden comment: C0603C225M8PACTU)
C153  ValueDisplayed: 47µF  [0805_HV]  (hidden comment: GRM21BR61A476ME15)
C154  ValueDisplayed: 47pF  [0603]  (hidden comment: CGA3E2C0G1H470J080AA)
C161  ValueDisplayed: 10µF  [1210]  (hidden comment: GRM32ER71H106KA12L)
C162  ValueDisplayed: 0.1µF  [1206]  (hidden comment: C1206C104J5RACTU)
C163  ValueDisplayed: 22µF  [0805_HV]  (hidden comment: GRM21BR61E226ME44L)
C164  ValueDisplayed: 0.1µF  [1206]  (hidden comment: C1206C104J5RACTU)
C165  ValueDisplayed: 1µF  [0603]  (hidden comment: GRM185C80J105KE26D)
C171  ValueDisplayed: 10µF  [0603]  (hidden comment: C1608X5R1E106M080AC)
C172  ValueDisplayed: 0.1µF  [0805_HV]  (hidden comment: C2012X7R2A104K125AA)
C173  ValueDisplayed: 0.01µF  [0603]  (hidden comment: 0603ZC103KAT2A)
D3  value 4.7V  [SOD-523]  (hidden comment: BZT52C4V7T-7)
D4  value 4.7V  [SOD-523]  (hidden comment: BZT52C4V7T-7)
J4  1751248  [CONN_1751248]
J18  1751248  [CONN_1751248]
J19  1751248  [CONN_1751248]
J20  1751248  [CONN_1751248]
L15  74437324010  ValueDisplayed: 1µH  [IND_WE-LHMI-4020]
L16  7447789002  [WE-PD_7332_PlasticBase]
Q3  CSD18504Q5A  [DQJ0008A]
Q4  CSD18504Q5A  [DQJ0008A]
R110  ValueDisplayed: 10.0k  [0603]  (hidden comment: CRCW060310K0FKEA)
R115  ValueDisplayed: 10.0k  [0603]  (hidden comment: CRCW060310K0FKEA)
R122  ValueDisplayed: 100k  [0603]  (hidden comment: RG1608P-104-B-T5)
R123  ValueDisplayed: 19.1k  [0603]  (hidden comment: RC0603FR-0719K1L)
R124  ValueDisplayed: 24.3k  [0603]  (hidden comment: RC0603FR-0724K3L)
R154  ValueDisplayed: 0  [0603]  (hidden comment: ERJ-3GEY0R00V)
R155  ValueDisplayed: 10.0k  [0603]  (hidden comment: ERJ-3EKF1002V)
R156  ValueDisplayed: 13.7k  [0603]  (hidden comment: RC0603FR-0713K7L)
R157  ValueDisplayed: 100k  [0603]  (hidden comment: ERA-3ARW104V)
R158  ValueDisplayed: 100k  [0603]  (hidden comment: ERA-3ARW104V)
R159  ValueDisplayed: 0  [0603]  (hidden comment: ERJ-3GEY0R00V)
R166  ValueDisplayed: 0  [0805_HV]  (hidden comment: CRCW08050000Z0EA)
R168  ValueDisplayed: 30.9k  [0603]  (hidden comment: RC0603FR-0730K9L)
R169  ValueDisplayed: 10.0k  [0603]  (hidden comment: ERJ-3EKF1002V)
TP20  (no value)  [Keystone5000]
TP41  5000  [Keystone5000]  (value not drawn)
TP43  5001  [Keystone5001]  (value not drawn)
TP68  (no value)  [Keystone5000]
TP69  5001  [Keystone5001]  (value not drawn)
TP91  5000  [Keystone5000]  (value not drawn)
TP92  5002  [Keystone5002]  (value not drawn)
TP93  5001  [Keystone5001]  (value not drawn)
TP94  5002  [Keystone5002]  (value not drawn)
TP95  5000  [Keystone5000]  (value not drawn)
TP96  5001  [Keystone5001]  (value not drawn)
U28  LM5050-2  [tsop-6]
U30  LM5050-2  [tsop-6]
U32  LM73605RNPR  [RNP0030A]
U39  TPS54325PWPR  [PWP0014E_N]
U42  TPS7A8001ADRBR  [DRB0008A]

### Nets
24V_S: R166.2
GND: C127.2(-) C128.2 C129.2 C130.2 C139.2(-) C140.2 C141.2 C142.2 C150.2 C151.2 C152.1 C153.2 C161.2 C163.2 C164.1 C165.1 C171.2 C172.2 C173.2 D3.2(A) D4.2(A) J4.1 J18.2 J19.2 J20.1 R123.1 R124.1 R155.1 R159.1 R169.1 TP43.1 TP69.1 TP93.1 TP96.1 U28.2(GND) U28.3(OFF) U30.2(GND) U30.3(OFF) U32.8(BIAS) U32.12(NC) U32.13(NC) U32.14(NC) U32.15(NC) U32.16(PGOOD) U32.17(SYNC) U32.19(AGND) U32.23(PGND) U32.24(PGND) U32.25(PGND) U32.26(PGND) U32.27(NC) U32.28(NC) U32.29(NC) U32.30(NC) U32.31(DAP) U39.5(GND) U39.8(PGND1) U39.9(PGND2) U39.15(PAD) U42.4(GND) U42.9(PAD)
SVC_5V: C153.1 C154.1 L15.2 R122.2 TP68.1 U42.5(EN) U42.7(IN) U42.8(IN)
NetC127_1: C127.1(+) C128.1 J18.1 Q3.1(S) Q3.2(S) Q3.3(S) U28.4(IN)
NetC129_1: C129.1 C130.1 C141.1 C142.1 J19.1 Q3.5(D) Q3.6(D) Q3.7(D) Q3.8(D) Q3.9(D) Q4.5(D) Q4.6(D) Q4.7(D) Q4.8(D) Q4.9(D) R110.1 R115.1 R154.1 TP41.1 TP95.1 U28.6(OUT) U30.6(OUT)
NetC139_1: C139.1(+) C140.1 J20.2 Q4.1(S) Q4.2(S) Q4.3(S) U30.4(IN)
NetC149_1: C149.1 U32.6(CBOOT)
NetC149_2: C149.2 L15.1 U32.1(SW) U32.2(SW) U32.3(SW) U32.4(SW) U32.5(SW)
NetC150_1: C150.1 C151.1 R166.1 U32.18(EN) U32.20(VIN) U32.21(VIN) U32.22(VIN)
NetC152_2: C152.2 U32.7(VCC)
NetC154_2: C154.2 R122.1 R124.2 U32.11(FB)
NetC161_1: C161.1 R154.2 R158.2 U39.13(VIN) U39.14(VCC)
NetC162_1: C162.1 U39.12(VBST)
NetC162_2: C162.2 L16.1 U39.10(SW1) U39.11(SW2)
NetC163_1: C163.1 J4.2 L16.2 R156.2 TP91.1 U39.1(VO)
NetC164_2: C164.2 U39.4(SS)
NetC165_2: C165.2 R157.1 TP92.1 U39.3(VREG5)
NetC171_1: C171.1 C172.1 R168.2 TP20.1 U42.1(OUT) U42.2(OUT)
NetC173_1: C173.1 U42.6(NR)
NetD3_1: D3.1(K) R110.2 U28.1(nFGD)
NetD4_1: D4.1(K) R115.2 U30.1(nFGD)
NetQ3_4: Q3.4(G) U28.5(GATE)
NetQ4_4: Q4.4(G) U30.5(GATE)
NetR123_2: R123.2 U32.9(RT)
NetR155_2: R155.2 R156.1 U39.2(VFB)
NetR157_2: R157.2 U39.6(PG)
NetR158_1: R158.1 R159.2 TP94.1 U39.7(EN)
NetR168_1: R168.1 R169.2 U42.3(FB)

Not connected (* = marked no-connect by the designer): U32 10(SS/TRK)*

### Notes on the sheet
- (near TP20) 3.3V
- Synchronous Stepdown VConverter
- To TPS5410 EVM
- (near TP91) 1.8V
- Redundant Supply

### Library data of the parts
C127 C139 = EKZE250ELL681MJ20S: CAP, AL, 680 µF, 25 V, +/- 20%, TH; Manufacturer: Chemi-Con; Polarized: Y; CompType: Capacitor; Value: 680uF; U/M: EA; Cap_F: 0.00068; Tolerance_%: 20; VDC_V: 25; Value2: 25V; IRMS_A: 1.82; TaMin_C: -40; TaMax_C: 105; Cap_Case: 10x20; SizeAreaWB_mm2: 144; SizeArea_mm2: 100; SizeX_mm: 10; SizeZ_mm: 21.5; AEC Category: Q200; AEC Qualified: N; Green_Lifecycle: Active; Green_REACh: Passed
C128 C140 = GRM188R61H105KAALD: CAP, CERM, 1 µF, 50 V, +/- 10%, X5R, 0603; Manufacturer: MuRata; Polarized: N; CompType: Capacitor; Value: 1uF; U/M: EA; Cap_F: 0.000001; Tolerance_%: 10; Value1: Unknown; VDC_V: 50; Value2: 50V; TaMin_C: -55; TaMax_C: 85
C129 C141 = C3216X7R1H105K: CAP, CERM, 1 µF, 50 V, +/- 10%, X7R, 1206; Manufacturer: TDK; Polarized: N; CompType: Capacitor; Value: 1uF; U/M: EA; Cap_F: 0.000001; Tolerance_%: 10; ESR_ohm: 0.01; Value1: 0.01 ohm; VDC_V: 50; Value2: 50V; IRMS_A: 3.2; TaMin_C: -55; TaMax_C: 125
C130 C142 = C1206C104J5RACTU: CAP, CERM, 0.1 µF, 50 V, +/- 5%, X7R, 1206; Manufacturer: Kemet; Polarized: N; CompType: Capacitor; Value: 0.1uF; U/M: EA; Cap_F: 0.0000001; Tolerance_%: 5; ESR_ohm: 0.059; Value1: 0.059 ohm; VDC_V: 50; Value2: 50V; IRMS_A: 1.2; TaMin_C: -55; TaMax_C: 125
C149 C151 = C1608X7R1H474K080AC: CAP, CERM, 0.47 µF, 50 V,+/- 10%, X7R, 0603; Manufacturer: TDK; Polarized: N; CompType: Capacitor; Value: 0.47uF; U/M: EA; Cap_F: 0.00000047; Tolerance_%: 10; ESR_ohm: 0.010974; Value1: 0.010974 ohm; VDC_V: 50; Value2: 50V; IRMS_A: 1.57483; TaMin_C: -55; TaMax_C: 125; SizeArea_mm2: 1.28; SizeAreaWB_mm2: 4.68; SizeX_mm: 1.6; SizeY_mm: 0.8; SizeZ_mm: 1; AEC Category: Q200; Green_Lifecycle: Active; Green_REACh: Passed
C150 = GRM32ER71H106KA12L: CAP, CERM, 10 µF, 50 V,+/- 10%, X7R, 1210; Manufacturer: MuRata; Polarized: N; CompType: Capacitor; Value: 10uF; U/M: EA; Cap_F: 0.00001; Tolerance_%: 10; VDC_V: 50; Value2: 50V; TaMin_C: -55; TaMax_C: 125; Cap_Case: 1210; SizeArea_mm2: 8; SizeAreaWB_mm2: 14.7; SizeX_mm: 3.2; SizeY_mm: 2.5; SizeZ_mm: 2.7; AEC Category: Q200; Green_Lifecycle: Active; Green_REACh: Passed
C152 = C0603C225M8PACTU: CAP, CERM, 2.2 µF, 10 V,+/- 20%, X5R, 0603; Manufacturer: Kemet; Polarized: N; CompType: Capacitor; Value: 2.2uF; U/M: EA; Cap_F: 0.0000022; Tolerance_%: 20; VDC_V: 10; Value2: 10V; TaMin_C: -55; TaMax_C: 85; SizeArea_mm2: 1.28; SizeAreaWB_mm2: 4.68; SizeX_mm: 1.6; SizeY_mm: 0.8; SizeZ_mm: 1; AEC Category: Q200; Green_Lifecycle: Active; Green_REACh: Passed
C153 = GRM21BR61A476ME15: CAP, CERM, 47 µF, 10 V,+/- 20%, X5R, 0805; Manufacturer: MuRata; Polarized: N; CompType: Capacitor; Value: 47uF; U/M: EA; Cap_F: 0.000047; Tolerance_%: 20; VDC_V: 10; Value2: 10V; TaMin_C: -55; TaMax_C: 85; Cap_Case: 0805; SizeArea_mm2: 2.5; SizeAreaWB_mm2: 6.75; SizeX_mm: 2; SizeY_mm: 1.25; SizeZ_mm: 1.45; AEC Category: Q200; Green_Lifecycle: Active; Green_REACh: Passed
C154 = CGA3E2C0G1H470J080AA: CAP, CERM, 47 pF, 50 V,+/- 5%, C0G/NP0, AEC-Q200 Grade 1, 0603; Manufacturer: TDK; Polarized: N; CompType: Capacitor; Value: 47pF; U/M: EA; Cap_F: 0.000000000047; Tolerance_%: 5; VDC_V: 50; Value2: 50V; TaMin_C: -55; TaMax_C: 125; SizeArea_mm2: 1.28; SizeAreaWB_mm2: 4.68; SizeX_mm: 1.6; SizeY_mm: 0.8; SizeZ_mm: 1; AEC Category: Q200; AEC Qualified: Y
C161 = GRM32ER71H106KA12L: CAP, CERM, 10 µF, 50 V, +/- 10%, X7R, 1210; Manufacturer: MuRata; Polarized: N; CompType: Capacitor; Value: 10uF; U/M: EA; Cap_F: 0.00001; Tolerance_%: 10; Value1: Unknown; VDC_V: 50; Value2: 50V; TaMin_C: -55; TaMax_C: 125
C162 C164 = C1206C104J5RACTU: CAP, CERM, 0.1 µF, 50 V,+/- 5%, X7R, 1206; Manufacturer: Kemet; Polarized: N; CompType: Capacitor; Value: 0.1uF; U/M: EA; Cap_F: 0.0000001; Tolerance_%: 5; ESR_ohm: 0.059; Value1: 0.059 ohm; VDC_V: 50; Value2: 50V; IRMS_A: 1.2; TaMin_C: -55; TaMax_C: 125; SizeArea_mm2: 5.12; SizeAreaWB_mm2: 10.92; SizeX_mm: 3.2; SizeY_mm: 1.6; SizeZ_mm: 1.35; AEC Category: Q200; Green_Lifecycle: Active; Green_REACh: Passed
C163 = GRM21BR61E226ME44L: CAP, CERM, 22 µF, 25 V,+/- 20%, X5R, 0805; Manufacturer: MuRata; Polarized: N; CompType: Capacitor; Value: 22uF; U/M: EA; Cap_F: 0.000022; Tolerance_%: 20; VDC_V: 25; Value2: 25V; TaMin_C: -55; TaMax_C: 85; Cap_Case: 0805; SizeArea_mm2: 2.5; SizeAreaWB_mm2: 6.75; SizeX_mm: 2; SizeY_mm: 1.25; SizeZ_mm: 1.45; AEC Category: Q200; Green_Lifecycle: Active; Green_REACh: Passed
C165 = GRM185C80J105KE26D: CAP, CERM, 1 µF, 6.3 V,+/- 10%, X6S, 0603; Manufacturer: MuRata; Polarized: N; CompType: Capacitor; Value: 1uF; U/M: EA; Cap_F: 0.000001; Tolerance_%: 10; VDC_V: 6.3; Value2: 6.3V; TaMin_C: -55; TaMax_C: 105; SizeArea_mm2: 1.28; SizeAreaWB_mm2: 4.68; SizeX_mm: 1.6; SizeY_mm: 0.8; SizeZ_mm: 1; AEC Category: Q200; Green_Lifecycle: Active; Green_REACh: Passed
C171 = C1608X5R1E106M080AC: as C62 on sheet TIDA-010011-E1_Processor_Power _Pg5
C172 = C2012X7R2A104K125AA: as C56 on sheet TIDA-010011-E1_Processor_Power _Pg5
C173 = 0603ZC103KAT2A: CAP, CERM, 0.01 µF, 10 V,+/- 10%, X7R, 0603; Manufacturer: AVX; Polarized: N; CompType: Capacitor; Value: 0.01uF; U/M: EA; Cap_F: 0.00000001; Tolerance_%: 10; Value2: 10V; TaMin_C: -55; TaMax_C: 125; SizeArea_mm2: 1.28; SizeAreaWB_mm2: 4.68; SizeX_mm: 1.6; SizeY_mm: 0.8; SizeZ_mm: 1; AEC Category: Q200; Green_Lifecycle: Active; Green_REACh: Passed
D3 D4 = BZT52C4V7T-7: Diode, Zener, 4.7 V, 300 mW, SOD-523; Manufacturer: Diodes Inc.; U/M: EA; SymbolCreator: a0412235; Power_W: 0.3; Vz_V: 4.7; Value1: 0.3W; RJA_CperW: 417
J4 J18-J20 = 1751248: as J3 on sheet TIDA-010011-E1_Processor_Power _Pg5
L15 = 74437324010: Inductor, Shielded Drum Core, Powdered Iron, 1uH, 5A, 0.022 ohm, SMD; Manufacturer: Wurth Elektronik eiSos; Ind_H: 1.0E-6; Imax_A: 5; Irms: 5A @ 40C rise; Isat: 9A @ 20% inductance drop; DCR_ohm: 0.022; U/M: EA
L16 = CMP-0064289-1: Inductor, Shielded Drum Core, Ferrite, 2.2 uH, 4.02 A, 0.019 ohm, SMD; Manufacturer: Wurth Elektronik; Isat: 4.8A @ 10% inductance drop; Irms: 4.02A @ 40C rise; Green_Lifecycle: Active; SizeAreaWB_mm2: 86.49; DCR_ohm: 0.019; Green_REACh: Passed; Value: 2.2uH; Imax_A: 4.02A; SizeZ_mm: 3.2; SizeX_mm: 7.3; SizeArea_mm2: 53.29; Ind_H: 2.2µH; AEC Category: Q200
Q3 Q4 = CMP-0000708-1: MOSFET, N-CH, 40 V, 15 A, DQJ0008A (VSONP-8); Alternate Manufacturer: None; Manufacturer: Texas Instruments; SizeZ_mm: 1.1; ChType: N; Value2: 7.7 nC; Value1: 0.009; VdsMax_V: 40V; SizeX_mm: 6; SizeY_mm: 4.9; Vgs_V: 20V; Value: 40V; Rdson45_ohm: 9.8m; SizeArea_mm2: 29.4; AEC Category: Q101; IdsMax_A: 15A; SizeAreaWB_mm2: 55.2; U/M: EA; QgTyp_nC: 7.7
R110 R115 = CRCW060310K0FKEA: RES, 10.0 k, 1%, 0.1 W, 0603; Manufacturer: Vishay-Dale; CompType: Resistor; Value: 10.0k; U/M: EA; Res_ohm: 10000; Value_Code: 10k0; Tolerance_%: 1; Power_W: 0.1; Value2: 0.1W; VDC_V: 75; TempCo: 100 ppm/C; EIA_Code: E96
R122 = RG1608P-104-B-T5: RES, 100 k, 0.1%, 0.1 W, 0603; Manufacturer: Susumu Co Ltd; CompType: Resistor; Value: 100k; Res_ohm: 100000; Tolerance_%: 0.1; Value2: 0.1W; VDC_V: 75; TempCo: 25 ppm/C; SizeArea_mm2: 1.28; SizeX_mm: 1.6; SizeY_mm: 0.8; SizeZ_mm: 1; EIA_Code: E192; U/M: EA; AEC Category: Q200; Green_Lifecycle: Active; Green_REACh: Passed
R123 = RC0603FR-0719K1L: RES, 19.1 k, 1%, 0.1 W, 0603; Manufacturer: Yageo America; CompType: Resistor; Value: 19.1k; Res_ohm: 19100; Value_Code: 19k1; Tolerance_%: 1; Power_W: 0.1; Value2: 0.1W; VDC_V: 150; TempCo: 200 ppm/C; SizeArea_mm2: 1.28; SizeX_mm: 1.6; SizeY_mm: 0.8; EIA_Code: E96; U/M: EA; AEC Category: Q200
R124 = RC0603FR-0724K3L: RES, 24.3 k, 1%, 0.1 W, 0603; Manufacturer: Yageo America; CompType: Resistor; Value: 24.3k; Res_ohm: 24300; Value_Code: 24k3; Tolerance_%: 1; Power_W: 0.1; Value2: 0.1W; VDC_V: 150; TempCo: 200 ppm/C; SizeArea_mm2: 1.28; SizeX_mm: 1.6; SizeY_mm: 0.8; EIA_Code: E96; U/M: EA; AEC Category: Q200
R154 R159 = ERJ-3GEY0R00V: RES, 0, 5%, 0.1 W, 0603; Manufacturer: Panasonic; CompType: Resistor; Value: 0; Value_Code: 0000; Tolerance_%: 5; Power_W: 0.1; Value2: 0.1W; VDC_V: 50; TempCo: 600 ppm/C; SizeArea_mm2: 1.28; SizeX_mm: 1.6; SizeY_mm: 0.8; SizeZ_mm: 1; EIA_Code: E24; U/M: EA; AEC Category: Q200; Green_Lifecycle: Active; Green_REACh: Passed
R155 R169 = ERJ-3EKF1002V: RES, 10.0 k, 1%, 0.1 W, 0603; Manufacturer: Panasonic; CompType: Resistor; Value: 10.0k; Res_ohm: 10000; Value_Code: 10k0; Tolerance_%: 1; Power_W: 0.1; Value2: 0.1W; VDC_V: 75; TempCo: 100 ppm/C; SizeArea_mm2: 1.28; SizeX_mm: 1.6; SizeY_mm: 0.8; EIA_Code: E96; U/M: EA; AEC Category: Q200; Green_Lifecycle: Active; Green_REACh: Passed
R156 = RC0603FR-0713K7L: RES, 13.7 k, 1%, 0.1 W, 0603; Manufacturer: Yageo America; CompType: Resistor; Value: 13.7k; Res_ohm: 13700; Value_Code: 13k7; Tolerance_%: 1; Power_W: 0.1; Value2: 0.1W; VDC_V: 150; TempCo: 200 ppm/C; SizeArea_mm2: 1.28; SizeX_mm: 1.6; SizeY_mm: 0.8; EIA_Code: E96; U/M: EA; AEC Category: Q200; Green_Lifecycle: Active; Green_REACh: Passed
R157 R158 = ERA-3ARW104V: RES, 100 k, 0.05%, 0.1 W, AEC-Q200 Grade 0, 0603; Manufacturer: Panasonic; CompType: Resistor; Value: 100k; Res_ohm: 100000; Tolerance_%: 0.05; Power_W: 0.1; Value2: 0.1W; VDC_V: 75; TempCo: 10 ppm/C; SizeArea_mm2: 1.28; SizeX_mm: 1.6; SizeY_mm: 0.8; SizeZ_mm: 1; U/M: EA; AEC Category: Q200; AEC Qualified: Y; AEC Grade: 0
R166 = CRCW08050000Z0EA: as R167 on sheet TIDA-010011-E1_Processor_Power _Pg5
R168 = RC0603FR-0730K9L: RES, 30.9 k, 1%, 0.1 W, 0603; Manufacturer: Yageo America; CompType: Resistor; Value: 30.9k; Res_ohm: 30900; Value_Code: 30k9; Tolerance_%: 1; Power_W: 0.1; Value2: 0.1W; VDC_V: 150; TempCo: 200 ppm/C; SizeArea_mm2: 1.28; SizeX_mm: 1.6; SizeY_mm: 0.8; EIA_Code: E96; U/M: EA; AEC Category: Q200; Green_Lifecycle: Active; Green_REACh: Passed
TP20 TP68 = 5000: as TP14-TP16 on sheet TIDA-010011-E1_Processor_Power _Pg5
TP41 TP91 TP95 = 5000: Test Point, Miniature, Red, TH; Manufacturer: Keystone; CompType: Test Point Loop; U/M: EA
TP43 TP93 TP96 = 5001: Test Point, Miniature, Black, TH; Manufacturer: Keystone; CompType: Test Point Loop; U/M: EA
TP69 = 5001: as TP17 on sheet TIDA-010011-E1_Processor_Power _Pg5
TP92 TP94 = 5002: as TP51 on sheet TIDA-010011-E1_Processor_Power _Pg5
U28 U30 = LM5050-2: HIGH SIDE OR-ING FET CONTROLLER; Manufacturer: Used in BOM report; SymbolVersion: use current date i.e. 2008-05-20; SymbolCreator: Use LDAP id; CompType: Used in some BOM reports.  Useful for finding later.; U/M: EA, IN, or GM
U32 = CMP-0013935-4: 3.5V to 36V 5A Synchronous Step-Down Voltage Regulator, RNP0030A (WQFN-30); Manufacturer: Texas Instruments; Alternate PartNumber: LM73605RNPRT; SizeX_mm: 4; SizeY_mm: 6; CompType: IC; SizeZ_mm: 0.8; SizeArea_mm2: 24; SizeAreaWB_mm2: 48; AEC Category: Q200; AEC Qualified: N
U39 = CMP-0067031-2: IC REG BUCK ADJ 3A SYNC 14HTSSOP; Manufacturer: Texas Instruments; Alternate PartNumber: TPS54225PWP; SizeX_mm: 6.4; SizeY_mm: 5.0; SizeZ_mm: 1.2; SizeArea_mm2: 32.0; SizeAreaWB_mm2: 58.8; U/M: EA; Green_Lifecycle: Active; Green_REACh: Passed
U42 = CMP-0065176-3: Low-Noise, High-Bandwidth PSRR, 1A Low-Dropout Linear Regulator, DRB0008A (VSON-8); Alternate PartNumber: TPS7A8001ADRBT; Manufacturer: Texas Instruments; SizeZ_mm: 1.0; SizeX_mm: 3.0; SizeArea_mm2: 9.0; CompType: IC; U/M: EA; SizeAreaWB_mm2: 16.0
